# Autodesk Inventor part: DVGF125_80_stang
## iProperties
Created: 2010-04
Part Number: DVGF125_80_stang
Document SubType Name: Modeling
Designer: TB
Mass: 1842.6 g
Surface Area: 1077.99 cm^2
Volume: 1842.6 cm^3
Density: 1 g/cm^3
Author: TB
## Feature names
1. Revolution1
2. Fillet1
3. Revolution2
4. Extrusion1
5. Extrusion2
6. Chamfer1
7. Fillet2
8. Chamfer3
